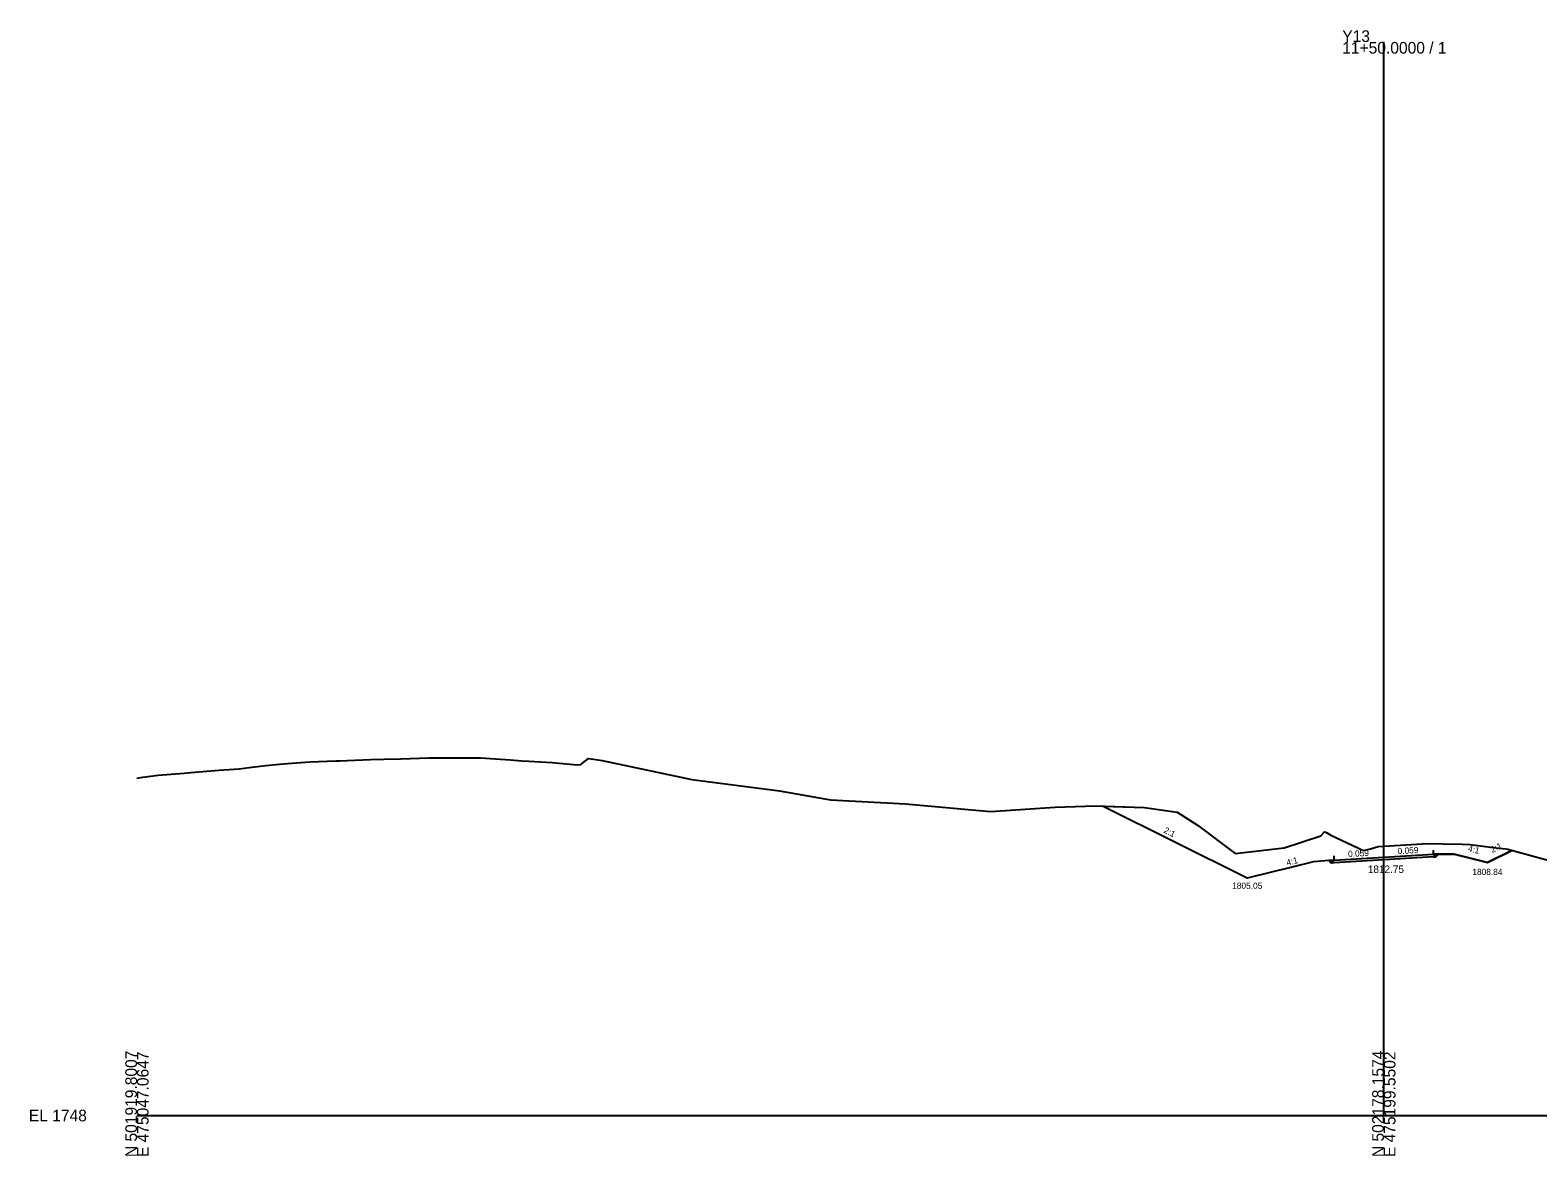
# Model space of a CAD drawing. Extents: x -126 to 503, y -10 to 2750.
# Drawn here: x -125.7 to 237.1, y 1490.3 to 1761 of the extents above; entities that cross this region are included whole.
import ezdxf

# ---------------------------------------------------------------- set-up
doc = ezdxf.new("R2010")
doc.units = 0
for name, color, linetype in [('Exist Cross Section Cell', 7, 'Continuous'), ('Exist XS Center Line Elevation Label', 7, 'Continuous'), ('Exist XS Ground Line', 7, 'Continuous'), ('Prop XS Ditch Slope Text', 7, 'Continuous'), ('Prop XS Ditch Standard Text', 7, 'Continuous'), ('Prop XS Dump Level', 7, 'Continuous'), ('Prop XS Earthwork Shape', 7, 'Continuous'), ('Prop XS EOT Tick Mark', 7, 'Continuous'), ('Prop XS Finish Grade', 7, 'Continuous'), ('Prop XS Finish Grade Earthwork', 7, 'Continuous'), ('Prop XS Finish Grade Pavement', 7, 'Continuous'), ('Prop XS Hydro Typical Ditch Data', 7, 'Continuous'), ('Prop XS Pvmt Edge Slope', 7, 'Continuous'), ('Prop XS SE Text', 7, 'Continuous'), ('Prop XS Shoulder Borrow Shape', 7, 'Continuous'), ('Prop XS Side Slope Text', 7, 'Continuous'), ('Prop XS Subgrade Earthwork', 7, 'Continuous')]:
    doc.layers.add(name, color=color, linetype=linetype)

msp = doc.modelspace()

# ---------------------------------------------------------------- linework, layer by layer
at = {"layer": 'Exist Cross Section Cell'}
for p, q in [((200, 1500), (200, 1758.18)), ((-100, 1500), (200, 1500)), ((200, 1500), (500, 1500))]:
    msp.add_line(p, q, dxfattribs=at)
at = {"layer": 'Exist XS Ground Line'}
msp.add_lwpolyline([(-100, 1581.17), (-98.61, 1581.37), (-94.91, 1581.86), (-88.66, 1582.37), (-87, 1582.5), (-80.32, 1583.04), (-75.38, 1583.4), (-73.02, 1583.68), (-69.02, 1584.14), (-65.72, 1584.53), (-63.77, 1584.68), (-58.43, 1585.08), (-52.17, 1585.28), (-51.14, 1585.34), (-49.39, 1585.42), (-43.84, 1585.65), (-40.56, 1585.7), (-36.54, 1585.76), (-29.75, 1586.03), (-28.95, 1586.05), (-27.78, 1586.06), (-17.34, 1586), (-10.12, 1585.58), (-7.36, 1585.27), (-5.74, 1585.21), (-0.07, 1584.89), (5.88, 1584.37), (6.84, 1584.44), (7.23, 1584.75), (8.64, 1585.87), (9.32, 1585.77), (11.48, 1585.46), (11.95, 1585.39), (33.5, 1580.85), (54.61, 1578.08), (66.87, 1575.93), (84.93, 1574.93), (105.35, 1573.1), (120.94, 1574.17), (130.54, 1574.48), (142.43, 1574.08), (150.29, 1572.97), (155.18, 1569.8), (164.21, 1563.05), (176, 1564.41), (184.82, 1567.3), (185.74, 1568.19), (186.24, 1568.05), (187.24, 1567.44), (195.11, 1563.76), (196.83, 1564.1), (198.64, 1564.66), (200, 1564.75), (209.32, 1565.35), (209.74, 1565.38), (218.86, 1565.27), (220.68, 1565.21), (227.71, 1564.26), (229.38, 1564.11), (229.83, 1564.02), (241.24, 1560.92)], dxfattribs=at)
at = {"layer": 'Prop XS Dump Level'}
for p, q in [((188.08, 1561.44), (200, 1562.15)), ((200, 1562.15), (211.92, 1562.85))]:
    msp.add_line(p, q, dxfattribs=at)
at = {"layer": 'Prop XS Earthwork Shape'}
msp.add_lwpolyline([(196.83, 1564.1), (198.64, 1564.66), (200, 1564.75), (209.32, 1565.35), (209.74, 1565.38), (218.86, 1565.27), (220.68, 1565.21), (227.71, 1564.26), (229.38, 1564.11), (229.83, 1564.02), (230.77, 1563.77), (224.92, 1560.84), (216.92, 1562.84), (213.17, 1562.85), (212.55, 1562.22), (211.92, 1562.18), (200, 1561.48), (188.08, 1560.78), (187.37, 1560.73), (186.77, 1561.34), (183.08, 1561.04), (167.1, 1557.05), (132.34, 1574.42), (142.43, 1574.08), (150.29, 1572.97), (155.18, 1569.8), (164.21, 1563.05), (176, 1564.41), (184.82, 1567.3), (185.74, 1568.19), (186.24, 1568.05), (187.24, 1567.44), (195.11, 1563.76)], close=True, dxfattribs=at)
at = {"layer": 'Prop XS EOT Tick Mark'}
for p, q in [((211.92, 1562.85), (211.92, 1563.85)), ((188.08, 1561.44), (188.08, 1562.44))]:
    msp.add_line(p, q, dxfattribs=at)
at = {"layer": 'Prop XS Finish Grade'}
for p, q in [((188.08, 1561.44), (186.77, 1561.34)), ((211.92, 1562.85), (213.17, 1562.85))]:
    msp.add_line(p, q, dxfattribs=at)
at = {"layer": 'Prop XS Finish Grade Earthwork'}
for p, q in [((167.1, 1557.05), (132.34, 1574.42)), ((224.92, 1560.84), (230.77, 1563.77)), ((183.08, 1561.04), (167.1, 1557.05)), ((186.77, 1561.34), (183.08, 1561.04)), ((213.17, 1562.85), (216.92, 1562.84)), ((216.92, 1562.84), (224.92, 1560.84))]:
    msp.add_line(p, q, dxfattribs=at)
at = {"layer": 'Prop XS Finish Grade Pavement'}
for p, q in [((188.08, 1561.44), (200, 1562.15)), ((200, 1562.15), (211.92, 1562.85))]:
    msp.add_line(p, q, dxfattribs=at)
at = {"layer": 'Prop XS Hydro Typical Ditch Data'}
for p, q in [((167.1, 1557.05), (132.34, 1574.42)), ((224.92, 1560.84), (230.77, 1563.77)), ((183.08, 1561.04), (175.08, 1559.04)), ((216.92, 1562.84), (224.92, 1560.84))]:
    msp.add_line(p, q, dxfattribs=at)
at = {"layer": 'Prop XS Pvmt Edge Slope'}
for p, q in [((188.08, 1561.44), (187.37, 1560.73)), ((211.92, 1562.85), (212.55, 1562.22))]:
    msp.add_line(p, q, dxfattribs=at)
at = {"layer": 'Prop XS Shoulder Borrow Shape'}
for points in [[(188.08, 1561.44), (187.37, 1560.73), (186.77, 1561.34)], [(212.55, 1562.22), (213.17, 1562.85), (211.92, 1562.85)]]:
    msp.add_lwpolyline(points, close=True, dxfattribs=at)
at = {"layer": 'Prop XS Subgrade Earthwork'}
for p, q in [((187.37, 1560.73), (186.77, 1561.34)), ((188.08, 1560.78), (187.37, 1560.73)), ((200, 1561.48), (188.08, 1560.78)), ((211.92, 1562.18), (200, 1561.48)), ((211.92, 1562.18), (212.55, 1562.22)), ((212.55, 1562.22), (213.17, 1562.85))]:
    msp.add_line(p, q, dxfattribs=at)

# ---------------------------------------------------------------- texts
at = {"layer": 'Exist Cross Section Cell'}
for s, p in [('Y13', (190, 1758.18)), ('11+50.0000 / 1', (190, 1755.38)), ('EL 1748', (-126, 1498.6))]:
    msp.add_text(s, height=2.8, dxfattribs=at).set_placement(p)
for s, p in [('N 501919.8007', (-100, 1490)), ('E 475047.0647', (-97.2, 1490)), ('N 502178.1574', (200, 1490)), ('E 475199.5502', (202.8, 1490))]:
    msp.add_text(s, height=2.8, rotation=90, dxfattribs=at).set_placement(p)
at = {"layer": 'Exist XS Center Line Elevation Label'}
msp.add_text('1812.75', height=1.8, dxfattribs=at).set_placement((196.15, 1558.33))
at = {"layer": 'Prop XS Ditch Slope Text'}
for rotation, p in [(345.9701, (220.13, 1563.59)), (14.0274, (176.76, 1560.06))]:
    msp.add_text('4:1', height=1.5, rotation=rotation, dxfattribs=at).set_placement(p)
at = {"layer": 'Prop XS Ditch Standard Text'}
for s, p in [('1808.84', (221.3, 1557.84)), ('1805.05', (163.51, 1554.52))]:
    msp.add_text(s, height=1.5, dxfattribs=at).set_placement(p)
at = {"layer": 'Prop XS Dump Level'}
for p in [(183.08, 1561), (216.92, 1562.8)]:
    msp.add_text('Case1', height=0.04, dxfattribs=at).set_placement(p)
at = {"layer": 'Prop XS SE Text'}
for rotation, p in [(3.3758, (191.44, 1562.14)), (3.3757, (203.36, 1562.84))]:
    msp.add_text('0.059', height=1.5, rotation=rotation, dxfattribs=at).set_placement(p)
at = {"layer": 'Prop XS Side Slope Text'}
for rotation, p in [(333.45, (146.89, 1568.11)), (26.5542, (226.11, 1563.12))]:
    msp.add_text('2:1', height=1.5, rotation=rotation, dxfattribs=at).set_placement(p)

doc.saveas('drawing.dxf')
